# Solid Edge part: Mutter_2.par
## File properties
Sűrűség: 0,000 kg/m^3
Pontosság: 0,990
Author: ahadarics
Last saved by: ahadarics
Revision: 77
Username: ahadarics
Dokumentum tartalom típus: 0
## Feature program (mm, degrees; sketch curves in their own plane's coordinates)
base feature "unnamed BaseFeature 1"
thread "unnamed Thread 1"
chamfer "unnamed Chamfer 1"
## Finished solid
Body 1: solid body, 13 faces, 24 edges, 12 vertices.
  Faces by surface: plane 8, cone 4, cylinder 1
  Edges by curve: spline 12, circle 6, line 6
Bounding box of the edges (mm): 25.403 x 22.000 x 6.000, from (-12.7017, -11, -3) to (12.7017, 11, 3).
Cylindrical faces by radius (mm): R7.188 x1
Conical faces (half-angle, radius in mm at the cone's reference point): 45 deg R7.188 x1, 45 deg R8.188 x1, 75 deg R12.75 x2
Planar faces by outward normal: +y 1, +z 1, -y 1, -z 1, oblique 4
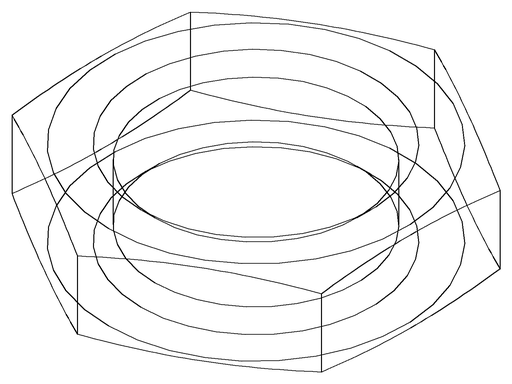
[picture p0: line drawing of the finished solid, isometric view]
